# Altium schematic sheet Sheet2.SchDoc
size A4
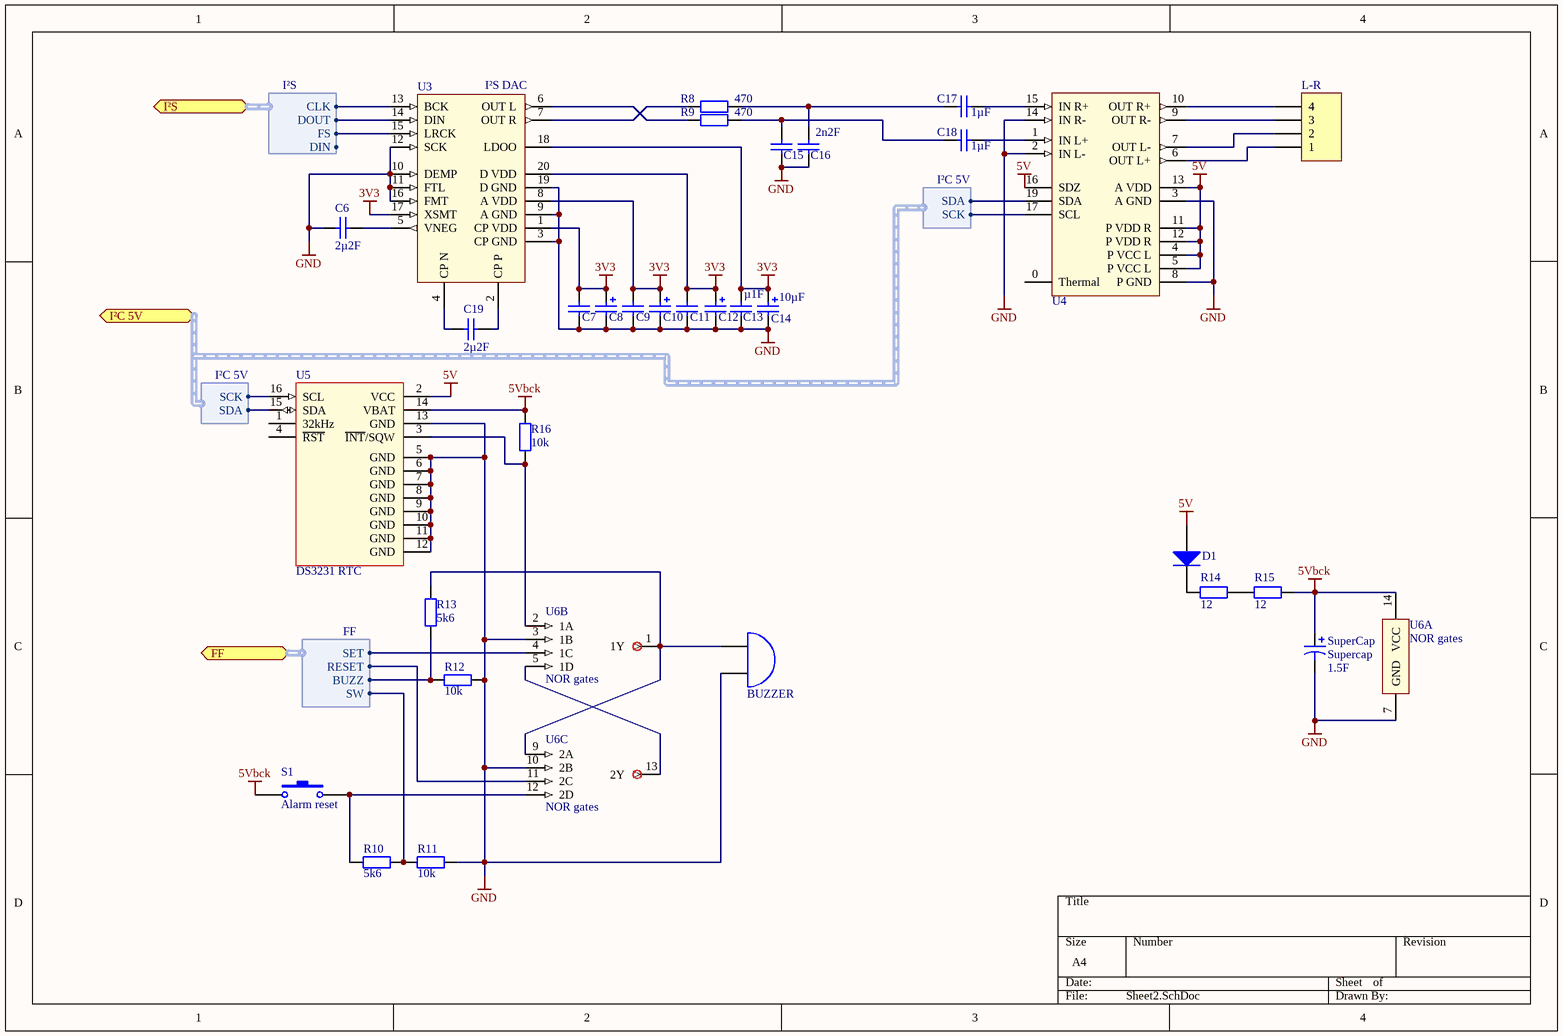
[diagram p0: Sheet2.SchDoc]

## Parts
BUZZER  (no value)  [HDR1X2]
C6  value 2µ2F  [C0805]
C7  value µ1F  [C0805]
C8  (no value)  [SMD cap 6x5]
C9  (no value)  [C0805]
C10  (no value)  [SMD cap 6x5]
C11  (no value)  [C0805]
C12  (no value)  [SMD cap 6x5]
C13  (no value)  [C0805]
C14  value 10µF  [SMD cap 6x5]
C15  (no value)  [C0805]
C16  value 2n2F  [C0805]
C17  value 1µF  [C0805]
C18  value 1µF  [C0805]
C19  value 2µ2F  [C0805]
D1  (no value)  [AXIAL-0.3]
L-R  Header 4  [HDR1X4]  (value not drawn)
R8  value 470  [C1206]
R9  value 470  [C1206]
R10  value 5k6  [C1206]
R11  value 10k  [C1206]
R12  value 10k  [C1206]
R13  value 5k6  [C1206]
R14  value 12  [C1206]
R15  value 12  [C1206]
R16  value 10k  [C1206]
S1  Alarm reset  [HDR1X2]
SuperCap  Supercap  value 1.5F  [HDR1X2]
U3  I²S DAC  [TSSOP-20]
U4  TPA2016D2  [QFN20-tpa2016d2]  (value not drawn)
U5  DS3231 RTC  [DS3231 SO-16]
U6  NOR gates  [SOIC-14]  (parts A,B,C of 3)

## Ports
FF (harness FF), I²C 5V (harness I²C 5V), I²S (harness I²S)

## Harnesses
I²S: CLK, FS, DOUT, DIN
I²C 5V: SCK, SDA
FF: SET, RESET, BUZZ, SW

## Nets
3V3: C7.1 C8.1 C9.1 C10.1 C11.2 C12.1 C13.1 C14.1 U3.1(CP_VDD) U3.8(A_VDD) U3.17(XSMT) U3.18(LDOO) U3.20(D_VDD)
5V: D1.1(A) U4.4(P_VCC_L) U4.5(P_VCC_L) U4.11(P_VDD_R) U4.12(P_VDD_R) U4.13(A_VDD) U4.16(SDZ) U5.2(VCC)
5Vbck: R15.2 R16.2 S1.1 SuperCap.1 U5.14(VBAT) U6.14(VCC)
GND: BUZZER.1(A) C6.1 C7.2 C8.2 C9.2 C10.2 C11.1 C12.2 C13.2 C14.2 C15.2 C16.2 R11.1 R12.1 SuperCap.2 U3.3(CP_GND) U3.9(A_GND) U3.10(DEMP) U3.11(FTL) U3.12(SCK) U3.16(FMT) U3.19(D_GND) U4.2(IN_L-) U4.3(A_GND) U4.8(P_GND) U4.14(IN_R-) U5.5(GND) U5.6(GND) U5.7(GND) U5.8(GND) U5.9(GND) U5.10(GND) U5.11(GND) U5.12(GND) U5.13(GND) U6.3(1B) U6.7(GND) U6.10(2B)
NetBUZZER_2: BUZZER.2(B) R13.1 U6.1(1Y) U6.9(2A)
NetC6_2: C6.2 U3.5(VNEG)
NetC15_1: C15.1 C18.2 R9.2
NetC16_1: C16.1 C17.2 R8.2
NetC17_1: C17.1 U4.15(IN_R+)
NetC18_1: C18.1 U4.1(IN_L+)
NetC19_1: C19.1 U3.2(CP_P)
NetC19_2: C19.2 U3.4(CP_N)
NetD1_2: D1.2(K) R14.1
NetL-R_1: L-R.1 U4.6(OUT_L+)
NetL-R_2: L-R.2 U4.7(OUT_L-)
NetL-R_3: L-R.3 U4.9(OUT_R-)
NetL-R_4: L-R.4 U4.10(OUT_R+)
NetR8_1: R8.1 U3.7(OUT_R)
NetR9_1: R9.1 U3.6(OUT_L)
NetR10_1: R10.1 R11.2 ; port FF.SW
NetR10_2: R10.2 S1.2 U6.12(2D)
NetR12_2: R12.2 R13.2 ; port FF.BUZZ
NetR14_2: R14.2 R15.1
NetR16_1: R16.1 U5.3(~{INT}/SQW) U6.2(1A)
NetU3_13: U3.13(BCK) ; port I²S.CLK
NetU3_14: U3.14(DIN) ; port I²S.DOUT
NetU3_15: U3.15(LRCK) ; port I²S.FS
NetU4_17: U4.17(SCL) U5.16(SCL) ; port I²C 5V.SCK
NetU4_19: U4.19(SDA) U5.15(SDA) ; port I²C 5V.SDA
NetU6_4: U6.4(1C) ; port FF.SET
NetU6_5: U6.5(1D) U6.13(2Y)
NetU6_11: U6.11(2C) ; port FF.RESET

Not connected (* = marked no-connect by the designer): U4 0(Thermal); U5 1(32kHz) 4(~{RST})

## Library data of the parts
BUZZER = Bell: Electrical Bell
C6 C7 C16-C19 = Cap: Capacitor
C8 C10 C12 = Cap Pol2: Polarized Capacitor (Axial); Value: 10µF
C9 C11 C13 = Cap: Capacitor; Value: 0.1µF
C14 = Cap Pol2: Polarized Capacitor (Axial)
C15 = Cap: Capacitor; Value: 2n2F
D1 = Diode: Default Diode
L-R = Header 4: Header, 4-Pin
R8-R16 = Res2: Resistor
S1 = SW-PB: Switch
SuperCap = Cap Pol1: Polarized Capacitor (Radial); pin to pad: 1>2 2>1
U3 = PCM5102A
U4 = TPA2016D2: I²C Audio Amplifier
U5 = DS3231: RTC
U6 = 744002: Dual 4-input NOR gate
